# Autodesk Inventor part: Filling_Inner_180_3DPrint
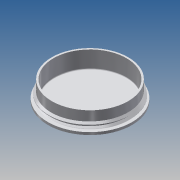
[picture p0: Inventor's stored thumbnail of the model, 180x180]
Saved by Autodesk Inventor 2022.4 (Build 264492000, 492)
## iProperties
Created: 2022-03
Part Number: Filling_Inner_180_3DPrint
Material: Aluminum 6061
Document SubType Name: Modeling
Designer: dotwibo2
Density: 2.71 g/cm^3
Appearance: Aluminum - Flat
Author: dotwibo2
Created: 2021-11
Part Number: Filling_Inner_180_short
Material: PLA filament White
Density: 1.384 g/cm^3
Appearance: White PLA
Mass: 214.853 g
Surface Area: 857.916 cm^2
Volume: 155.241 cm^3
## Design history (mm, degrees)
sketch "Sketch2"
  geometry: L1 (-7.4, 0)-(44.4, 0) reference; L2 (0, -16.6)-(0, 99.6) reference; L3 (3, 0)-(3, 72); L4 (0, 0)-(0, 83); L5 (0, 83)-(5, 83); L6 (5, 83)-(5, 75.375); L7 (3, 72)-(37, 72); L8 (37, 72)-(37, 75.375); L9 (37, 75.375)-(5, 75.375); 2 further points
  constraints: 14 end point, 4 vertical, 3 horizontal, 2 point on line, 1 collinear, 1 horizontal alignment
  dimensions: "d2" = 3 distance between parallel lines of L3 L2; "d3" = 37 distance between parallel lines of L2 L8; "d4" = 5 distance between parallel lines of L2 L6; "d5" = 144 diameter of L7 L1; "d6" = 166 diameter of L5 L1; "d54" = 150.75 diameter of L9 L1
revolve "Revolution1" sketch "Sketch2" stored, may be unused: angle "d9" = 90 deg
fillet "Fillet1" dims "d57" = 2
sketch "Sketch4"
  geometry: L1 (6, 82.039)-(2, 75.111); L2 (2, 75.111)-(-2, 82.039); L3 (-2, 82.039)-(-6, 75.111); L4 (-25.047, 0)-(76.328, 0) reference; L5 (0, -108.448)-(0, 125.298) reference; L6 (-6, 75.111)-(-10.082, 82.181); L7 (38.002, 75.111)-(19.603, 75.111); L8 (-2, 82.039)-(6, 82.039); L9 (61.846, -75.111)-(15.468, -75.111); L10 (2.499, 75.975)-(1.501, 75.975); L11 (2, 73.711)-(-1.501, 79.775); L12 (-2, 80.639)-(-2.499, 79.775); L13 (-6, 73.711)-(2, 73.711); L14 (-1.501, 79.775)-(-2.499, 79.775); L15 (2, 74.411)-(-2, 81.339); L16 (-2, 81.339)-(-6, 74.411); L17 (2, 74.411)-(11.616, 91.066); L18 (2, 73.711)-(12.504, 91.905); L19 (-6, 74.411)-(-0.583, 65.028); L20 (-6, 73.711)-(-8.164, 77.458); L21 (41.021, 77.875)-(-2.64, 77.875); L22 (44.753, 80.375)-(-10.082, 80.375); L23 (44.733, 75.375)-(-10.565, 75.375); L24 (-1.501, 79.775)-(-2, 80.639); L25 (-2.499, 79.775)-(-6, 73.711); 2 further points
  constraints: 46 end point, 13 parallel, 9 horizontal, 5 point on line, 1 midpoint, 1 vertical alignment, 5 other
  dimensions: "d10" = 30 deg angle of L5 L1; "d11" = 30 deg angle of L5 L2; "d12" = 2 distance from line of L5 L1.end; "d13" = 150.2218 diameter of L1.end L4 (derived); "d14" = 8 distance of L1.end L3.end; "d15" = 0.99778 distance of L10.start L10.end (derived); "d23" = 151.95 diameter of L10 L4 (derived); "d24" = 0.99778 distance of L11.end L12.end (derived); "d25" = 159.55 diameter of L14 L4 (derived); "d27" = 0.7 distance between parallel lines of L11 L2; "d29" = 155.75 diameter of L21 L4; "d58" = 160.75 diameter of L22 L4; "d59" = 0.6 distance between parallel lines of L14 L22; "d60" = 150.75 diameter of L23 L4 (= d54); "d61" = 0.6 distance between parallel lines of L23 L10
coil "Coil1" sketch "Sketch4" pitch "d30" = 8; turns "d32" = 1; dims "d31" = 45, "d33" = 0, angle "d34" = 90 deg, angle "d35" = 90 deg, "d36" = 0, "d37" = 0
sketch "Sketch5"
  geometry: L1 (8.959, 80.5)-(15.041, 80.5); L2 (15.041, 80.5)-(18, 75.375); L3 (18, 75.375)-(6, 75.375); L4 (6, 75.375)-(8.959, 80.5); L5 (-7.4, 0)-(44.4, 0) reference; L6 (0, -17)-(0, 102) reference; 1 further point
  constraints: 8 end point, 1 horizontal, 1 parallel
  dimensions: "d40" = 150.75 diameter of L3 L5 (= d54); "d45" = 161 diameter of L1 L5; "d46" = 18 distance from line of L6 L2.end; "d47" = 6 distance from line of L6 L3.end; "d55" = 60 deg angle of L3 L2; "d62" = 60 deg angle of L3 L4 (= d55)
revolve "Revolution2" sketch "Sketch5" stored, may be unused: angle "d41" = 90 deg
combine "Combine1"
  body "Solid4"
node "NEW_FILLING"
body "Solid1"
